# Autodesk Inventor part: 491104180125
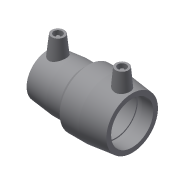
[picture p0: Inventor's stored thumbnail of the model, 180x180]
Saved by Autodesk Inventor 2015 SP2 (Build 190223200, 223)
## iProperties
Created: 2017-06
Part Number: 491104180125
Material: Generic
Description: PLASSON REDUCING COUPLER 180-125
Document SubType Name: Modeling
Designer: KIM
Mass: 54.8237 g
Surface Area: 155.252 cm^2
Volume: 54.8237 cm^3
Density: 1 g/cm^3
Appearance: Default
Author: KIM
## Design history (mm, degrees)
derived "491104.ipt"
feature "Solid1::491104.ipt"
tag "TaggingFeature1"
body "Solid1"
other parameters: "d0" = 212, "d2" = 158, "d3" = 85, "d4" = 51, "d5" = 142.2, "d7" = 125, "d8" = 168 deg, "d10" = 34, "d11" = 11.33333, "d13" = 212, "d14" = 17.6296, "d15" = 85, "d18" = 125, "d19" = 4.25, "d20" = 168 deg, "d22" = 108.92847, "d25" = 135 deg, "d29" = 87, "d30" = 15, "d31" = 74.2, "d34" = 6 deg, "d35" = 15, "d38" = 18.25, "d39" = 5 deg, "d41" = 4, "d42" = 14, "d43" = 0, "d45" = 4, "d46" = 14, "d47" = 0, "d48" = 158, "d50" = 222, "d52" = 112.5, "d53" = 41.2, "d54" = 13.73333, "d55" = 168 deg, "d56" = 61.8, "d57" = 103, "d58" = 199.8, "d59" = 4.25, "d60" = 135 deg, "d61" = 116, "d62" = 15, "d64" = 4, "d66" = 5 deg, "d67" = 14, "d68" = 0, "d69" = 74.2, "d70" = 158, "d71" = 222, "d73" = 208.68, "d76" = 4.25, "d77" = 168 deg, "d79" = 4.25, "d80" = 103, "d81" = 112.5, "d82" = 148.52, "d83" = 120 deg, "d88" = 15, "d89" = 17, "d90" = 5 deg, "d92" = 4, "d93" = 14, "d94" = 0, "d95" = 3, "d96" = 0, "d97" = 3, "d98" = 0, "d99" = 24.65, "d100" = 6.1625, "d101" = 144.0644, "d102" = 20 deg, "d103" = 29.87, "d104" = 7.4675, "d105" = 202.4196, "d106" = 3.60705, "d107" = 3, "d108" = 0, "d109" = 3, "d110" = 0, "d_1" = 125, "L_" = 212, "L_2" = 85, "D_1" = 158, "A_1" = 87, "d_2" = 12, "L_1" = 103, "A_" = 116, "D_" = 222
